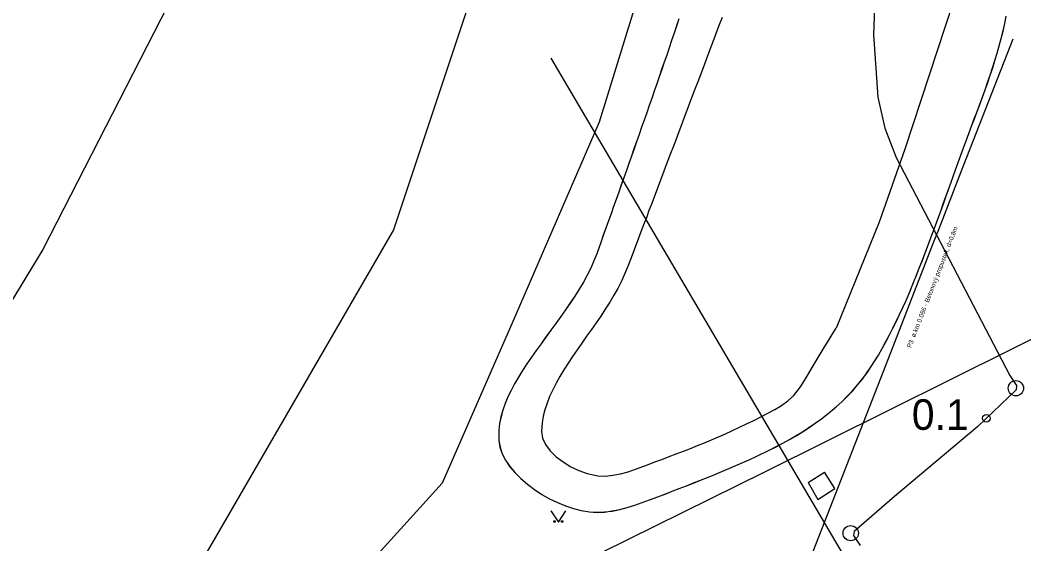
# Model space of a CAD drawing. Extents: x -737422 to -734235, y -1145631 to -1142623.
# Drawn here: x -735091.9 to -735026.3, y -1143091 to -1143056.7 of the extents above; entities that cross this region are included whole.
import ezdxf

# ---------------------------------------------------------------- set-up
doc = ezdxf.new("R2010")
doc.units = 0
for name, color, linetype in [('Vrstva 1', 7, 'Continuous'), ('Vrstva 2', 7, 'Continuous'), ('Vrstva 20', 7, 'Continuous'), ('Vrstva 22', 7, 'Continuous'), ('Vrstva 3', 7, 'Continuous'), ('Vrstva 40', 7, 'Continuous'), ('Vrstva 6', 7, 'Continuous'), ('Vrstva 7', 7, 'Continuous'), ('Vrstva 8', 7, 'Continuous')]:
    doc.layers.add(name, color=color, linetype=linetype)

# ---------------------------------------------------------------- blocks, each defined once
blk = doc.blocks.new('1.050')
at = {"layer": 'Vrstva 1'}
for radius in [0.5, 0.001]:
    blk.add_circle((0, 0), radius, dxfattribs=at)
blk = doc.blocks.new('6.200')
at = {"layer": 'Vrstva 1'}
blk.add_circle((0, 0), 1, dxfattribs=at)
blk = doc.blocks.new('3.140')
at = {"layer": 'Vrstva 1'}
blk.add_lwpolyline([(-1, 1.5), (0, 0), (1, 1.5)], dxfattribs=at)
for centre in [(-0.5, 0.1), (0.5, 0.1)]:
    blk.add_circle(centre, 0.1, dxfattribs=at)

msp = doc.modelspace()

# ---------------------------------------------------------------- linework, layer by layer
at = {"layer": 'Vrstva 2'}
for points in [[(-735047.84, -1142987.81), (-735035.74, -1143023.25), (-735035.52, -1143024.84), (-735035.34, -1143033.99), (-735035.46, -1143039.98), (-735036.11, -1143057.68), (-735035.82, -1143061.77), (-735035.37, -1143063.8), (-735034.62, -1143065.72), (-735027.19, -1143079.99), (-735026.74, -1143080.64), (-735026.77, -1143080.92), (-735029.28, -1143083.32), (-735034.74, -1143087.91), (-735037.38, -1143090.19), (-735037.41, -1143090.46), (-735036.99, -1143091.1)], [(-735062.19, -1143054.47), (-735067.52, -1143070.46), (-735083.15, -1143097.45), (-735109.45, -1143130.12), (-735117, -1143136.7), (-735131.48, -1143149.3), (-735161.32, -1143169.9), (-735197.01, -1143189.05), (-735200.15, -1143191.6), (-735226.32, -1143212.89), (-735242.32, -1143233.92), (-735251.01, -1143259.51), (-735252.721, -1143271.637)]]:
    msp.add_lwpolyline(points, dxfattribs=at)
at = {"layer": 'Vrstva 20'}
for points in [[(-735049.61, -1143048.97), (-735054.06, -1143063.41)], [(-735030.34, -1143053.87), (-735034.05, -1143065.18)], [(-735046.02, -1143056.56), (-735046.2, -1143057.03), (-735046.37, -1143057.5), (-735046.55, -1143057.97), (-735046.73, -1143058.43), (-735046.9, -1143058.9), (-735047.08, -1143059.37), (-735047.26, -1143059.84), (-735047.43, -1143060.3), (-735047.61, -1143060.77), (-735047.79, -1143061.24), (-735047.97, -1143061.71), (-735048.14, -1143062.17), (-735048.32, -1143062.64), (-735048.5, -1143063.11), (-735048.67, -1143063.58), (-735048.85, -1143064.04), (-735049.03, -1143064.51), (-735049.2, -1143064.98), (-735049.38, -1143065.45), (-735049.56, -1143065.92), (-735049.74, -1143066.38), (-735049.91, -1143066.85), (-735050.09, -1143067.32), (-735050.27, -1143067.79), (-735050.44, -1143068.25), (-735050.62, -1143068.72), (-735050.8, -1143069.19), (-735050.97, -1143069.66), (-735051.15, -1143070.12), (-735051.33, -1143070.59), (-735051.51, -1143071.06), (-735051.68, -1143071.53), (-735051.86, -1143071.99), (-735052.2, -1143072.89), (-735052.39, -1143073.36), (-735052.6, -1143073.82), (-735052.84, -1143074.28), (-735053.1, -1143074.73), (-735053.37, -1143075.19), (-735053.66, -1143075.64), (-735053.96, -1143076.09), (-735054.26, -1143076.54), (-735054.57, -1143076.98), (-735054.88, -1143077.42), (-735055.19, -1143077.86), (-735055.5, -1143078.3), (-735055.8, -1143078.74), (-735056.09, -1143079.18), (-735056.37, -1143079.61), (-735056.63, -1143080.05), (-735056.88, -1143080.48), (-735057.1, -1143080.92), (-735057.3, -1143081.35), (-735057.47, -1143081.79), (-735057.61, -1143082.22), (-735057.72, -1143082.65), (-735057.79, -1143083.09), (-735057.83, -1143083.64), (-735057.76, -1143084.08), (-735057.56, -1143084.5), (-735057.26, -1143084.91), (-735056.87, -1143085.3), (-735056.41, -1143085.64), (-735055.91, -1143085.95), (-735055.38, -1143086.2), (-735054.85, -1143086.39), (-735054.14, -1143086.54), (-735053.65, -1143086.56), (-735053.16, -1143086.51), (-735052.67, -1143086.42), (-735052.17, -1143086.28), (-735051.69, -1143086.12), (-735050.89, -1143085.82), (-735050.42, -1143085.64)], [(-735048.84, -1143056.64), (-735049, -1143057.11), (-735049.16, -1143057.59), (-735049.32, -1143058.06), (-735049.48, -1143058.54), (-735049.64, -1143059.01), (-735049.8, -1143059.48), (-735049.97, -1143059.96), (-735050.13, -1143060.43), (-735050.29, -1143060.9), (-735050.46, -1143061.38), (-735050.62, -1143061.85), (-735050.79, -1143062.32), (-735050.95, -1143062.8), (-735051.11, -1143063.27), (-735051.28, -1143063.74), (-735051.45, -1143064.21), (-735051.61, -1143064.69), (-735051.78, -1143065.16), (-735051.94, -1143065.63), (-735052.11, -1143066.1), (-735052.28, -1143066.57), (-735052.45, -1143067.05), (-735052.61, -1143067.52), (-735052.78, -1143067.99), (-735052.95, -1143068.46), (-735053.12, -1143068.93), (-735053.28, -1143069.4), (-735053.45, -1143069.87), (-735053.62, -1143070.34), (-735053.79, -1143070.81), (-735053.96, -1143071.28), (-735054.22, -1143072.02)], [(-735034.4, -1143075.99), (-735034.19, -1143075.53), (-735033.98, -1143075.08), (-735033.78, -1143074.62), (-735033.48, -1143073.89), (-735033.3, -1143073.42), (-735033.11, -1143072.96), (-735032.93, -1143072.49), (-735032.75, -1143072.03), (-735032.58, -1143071.56), (-735032.4, -1143071.09), (-735032.22, -1143070.63), (-735032.05, -1143070.16), (-735031.88, -1143069.69), (-735031.71, -1143069.22), (-735031.54, -1143068.75), (-735031.37, -1143068.28), (-735031.2, -1143067.81), (-735031.03, -1143067.34), (-735030.74, -1143066.52), (-735030.57, -1143066.05), (-735030.4, -1143065.57), (-735030.22, -1143065.09), (-735030.04, -1143064.62), (-735029.86, -1143064.14), (-735029.69, -1143063.67), (-735029.51, -1143063.19), (-735029.33, -1143062.71), (-735029.15, -1143062.24), (-735028.98, -1143061.76), (-735028.8, -1143061.28), (-735028.64, -1143060.8), (-735028.47, -1143060.33), (-735028.31, -1143059.85), (-735028.16, -1143059.37), (-735028.02, -1143058.89), (-735027.88, -1143058.4), (-735027.75, -1143057.92), (-735027.63, -1143057.44), (-735027.52, -1143056.95), (-735027.42, -1143056.47)], [(-735054.06, -1143063.41), (-735059.55, -1143076.11)], [(-735034.05, -1143065.18), (-735035.74, -1143069.94)], [(-735035.74, -1143069.94), (-735038.55, -1143076.88)], [(-735054.22, -1143072.02), (-735054.4, -1143072.49), (-735054.61, -1143072.95), (-735054.84, -1143073.42), (-735055.09, -1143073.87), (-735055.36, -1143074.33), (-735055.65, -1143074.79), (-735055.95, -1143075.24), (-735056.26, -1143075.69), (-735056.57, -1143076.13), (-735056.89, -1143076.58), (-735057.22, -1143077.02), (-735057.54, -1143077.46), (-735057.86, -1143077.9), (-735058.18, -1143078.34), (-735058.49, -1143078.78), (-735058.79, -1143079.22), (-735059.07, -1143079.65), (-735059.34, -1143080.09), (-735059.59, -1143080.52), (-735059.82, -1143080.96), (-735060.03, -1143081.39), (-735060.21, -1143081.82), (-735060.36, -1143082.25), (-735060.48, -1143082.69), (-735060.57, -1143083.12), (-735060.62, -1143083.55), (-735060.62, -1143084.24), (-735060.55, -1143084.67), (-735060.4, -1143085.11), (-735060.18, -1143085.53), (-735059.9, -1143085.95), (-735059.56, -1143086.35), (-735059.18, -1143086.73), (-735058.75, -1143087.1), (-735058.3, -1143087.44), (-735057.81, -1143087.76), (-735057.31, -1143088.05), (-735056.79, -1143088.3), (-735056.27, -1143088.51), (-735055.74, -1143088.69), (-735055.23, -1143088.82), (-735054.68, -1143088.91), (-735054.19, -1143088.94), (-735053.7, -1143088.92), (-735053.21, -1143088.85), (-735052.71, -1143088.75), (-735052.22, -1143088.62), (-735051.73, -1143088.47), (-735051.24, -1143088.3), (-735050.76, -1143088.13), (-735050.22, -1143087.92), (-735049.75, -1143087.74), (-735049.28, -1143087.56), (-735048.82, -1143087.38), (-735048.35, -1143087.2), (-735047.89, -1143087.02), (-735047.42, -1143086.83), (-735046.96, -1143086.65), (-735046.5, -1143086.46), (-735046.04, -1143086.27), (-735045.58, -1143086.08), (-735045.12, -1143085.88), (-735044.66, -1143085.68), (-735044.21, -1143085.47), (-735043.75, -1143085.26), (-735042.93, -1143084.87), (-735042.48, -1143084.64), (-735042.04, -1143084.41), (-735041.6, -1143084.17), (-735041.17, -1143083.92), (-735040.75, -1143083.66), (-735040.33, -1143083.39), (-735039.92, -1143083.11), (-735039.51, -1143082.82), (-735038.94, -1143082.37), (-735038.55, -1143082.04), (-735038.18, -1143081.7), (-735037.82, -1143081.34), (-735037.47, -1143080.98), (-735037.15, -1143080.6), (-735036.83, -1143080.21), (-735036.53, -1143079.81), (-735036.25, -1143079.4), (-735035.79, -1143078.65), (-735035.54, -1143078.21), (-735035.3, -1143077.77), (-735035.07, -1143077.33), (-735034.84, -1143076.88), (-735034.61, -1143076.43), (-735034.4, -1143075.99)], [(-735059.55, -1143076.11), (-735064.33, -1143087.02)], [(-735022.89, -1143076.19), (-735043.24, -1143086.3)], [(-735050.42, -1143085.64), (-735049.95, -1143085.47), (-735049.48, -1143085.29), (-735049.01, -1143085.11), (-735048.55, -1143084.93), (-735048.09, -1143084.75), (-735047.62, -1143084.57), (-735047.16, -1143084.38), (-735046.7, -1143084.19), (-735046.24, -1143083.99), (-735045.79, -1143083.79), (-735045.33, -1143083.58), (-735044.88, -1143083.37), (-735044.42, -1143083.15), (-735043.94, -1143082.92), (-735043.48, -1143082.69), (-735043.02, -1143082.45), (-735042.57, -1143082.21), (-735042.13, -1143081.94), (-735041.72, -1143081.65), (-735041.35, -1143081.32), (-735040.88, -1143080.73), (-735040.62, -1143080.3), (-735040.36, -1143079.88), (-735040.11, -1143079.45), (-735039.85, -1143079.02), (-735039.59, -1143078.59), (-735039.33, -1143078.16), (-735039.07, -1143077.74), (-735038.81, -1143077.31), (-735038.55, -1143076.88)], [(-735043.24, -1143086.3), (-735057.51, -1143093.35)], [(-735040.39, -1143086.99), (-735039.32, -1143086.31)], [(-735038.64, -1143087.38), (-735039.32, -1143086.31)], [(-735040.39, -1143086.99), (-735039.76, -1143088.09)], [(-735039.76, -1143088.09), (-735038.64, -1143087.38)]]:
    msp.add_lwpolyline(points, dxfattribs=at)
at = {"layer": 'Vrstva 3'}
for points in [[(-735034.121, -1142807.443), (-735041.41, -1142833.15), (-735049.67, -1142873.94), (-735063.61, -1142929.72), (-735068.77, -1142951.92), (-735071.87, -1143011.83), (-735079.1, -1143049.53), (-735090.46, -1143071.74), (-735105.06, -1143095.74), (-735128.12, -1143122.71), (-735156.5, -1143145.42), (-735208.29, -1143180.56), (-735229.22, -1143198.3), (-735243.77, -1143211.78), (-735256.18, -1143225.98), (-735267.54, -1143251.18), (-735270.892, -1143271.893)], [(-735049.61, -1143048.97), (-735054.06, -1143063.41)], [(-735048.835, -1143056.64), (-735048.995, -1143057.114), (-735049.156, -1143057.588), (-735049.317, -1143058.062), (-735049.478, -1143058.536), (-735049.64, -1143059.01), (-735049.803, -1143059.483), (-735049.965, -1143059.957), (-735050.129, -1143060.43), (-735050.292, -1143060.904), (-735050.456, -1143061.377), (-735050.62, -1143061.85), (-735050.785, -1143062.323), (-735050.949, -1143062.796), (-735051.114, -1143063.268), (-735051.28, -1143063.741), (-735051.446, -1143064.213), (-735051.611, -1143064.685), (-735051.778, -1143065.158), (-735051.944, -1143065.63), (-735052.111, -1143066.101), (-735052.278, -1143066.573), (-735052.445, -1143067.045), (-735052.612, -1143067.516), (-735052.779, -1143067.987), (-735052.947, -1143068.458), (-735053.115, -1143068.929), (-735053.282, -1143069.4), (-735053.45, -1143069.87), (-735053.619, -1143070.341), (-735053.787, -1143070.811), (-735053.955, -1143071.281), (-735054.22, -1143072.02)], [(-735034.396, -1143075.985), (-735034.185, -1143075.534), (-735033.98, -1143075.079), (-735033.782, -1143074.622), (-735033.48, -1143073.89), (-735033.295, -1143073.424), (-735033.112, -1143072.959), (-735032.932, -1143072.493), (-735032.752, -1143072.027), (-735032.575, -1143071.561), (-735032.399, -1143071.094), (-735032.224, -1143070.627), (-735032.051, -1143070.16), (-735031.878, -1143069.692), (-735031.707, -1143069.223), (-735031.537, -1143068.753), (-735031.367, -1143068.283), (-735031.198, -1143067.811), (-735031.03, -1143067.339), (-735030.74, -1143066.52), (-735030.57, -1143066.045), (-735030.397, -1143065.569), (-735030.221, -1143065.094), (-735030.043, -1143064.618), (-735029.864, -1143064.142), (-735029.685, -1143063.666), (-735029.505, -1143063.19), (-735029.326, -1143062.714), (-735029.149, -1143062.237), (-735028.975, -1143061.76), (-735028.803, -1143061.282), (-735028.635, -1143060.804), (-735028.472, -1143060.325), (-735028.314, -1143059.846), (-735028.162, -1143059.366), (-735028.017, -1143058.885), (-735027.879, -1143058.404), (-735027.75, -1143057.921), (-735027.629, -1143057.438), (-735027.518, -1143056.954), (-735027.418, -1143056.469)], [(-735054.06, -1143063.41), (-735059.55, -1143076.11)], [(-735054.22, -1143072.02), (-735054.402, -1143072.488), (-735054.61, -1143072.953), (-735054.842, -1143073.415), (-735055.094, -1143073.874), (-735055.364, -1143074.331), (-735055.649, -1143074.785), (-735055.948, -1143075.236), (-735056.256, -1143075.686), (-735056.573, -1143076.133), (-735056.894, -1143076.579), (-735057.218, -1143077.022), (-735057.542, -1143077.464), (-735057.863, -1143077.904), (-735058.179, -1143078.343), (-735058.488, -1143078.781), (-735058.785, -1143079.217), (-735059.07, -1143079.653), (-735059.339, -1143080.088), (-735059.59, -1143080.521), (-735059.821, -1143080.955), (-735060.027, -1143081.388), (-735060.208, -1143081.821), (-735060.36, -1143082.253), (-735060.482, -1143082.686), (-735060.569, -1143083.118), (-735060.62, -1143083.551), (-735060.62, -1143084.24), (-735060.546, -1143084.674), (-735060.397, -1143085.105), (-735060.178, -1143085.53), (-735059.897, -1143085.945), (-735059.561, -1143086.348), (-735059.178, -1143086.734), (-735058.753, -1143087.1), (-735058.295, -1143087.443), (-735057.81, -1143087.76), (-735057.305, -1143088.046), (-735056.788, -1143088.298), (-735056.265, -1143088.514), (-735055.744, -1143088.689), (-735055.231, -1143088.82), (-735054.68, -1143088.91), (-735054.193, -1143088.937), (-735053.702, -1143088.915), (-735053.208, -1143088.851), (-735052.714, -1143088.752), (-735052.22, -1143088.623), (-735051.728, -1143088.472), (-735051.241, -1143088.304), (-735050.759, -1143088.126), (-735050.22, -1143087.92), (-735049.752, -1143087.74), (-735049.284, -1143087.56), (-735048.818, -1143087.38), (-735048.352, -1143087.199), (-735047.887, -1143087.017), (-735047.424, -1143086.834), (-735046.961, -1143086.649), (-735046.499, -1143086.462), (-735046.039, -1143086.272), (-735045.579, -1143086.078), (-735045.12, -1143085.881), (-735044.662, -1143085.68), (-735044.206, -1143085.474), (-735043.75, -1143085.264), (-735042.93, -1143084.87), (-735042.48, -1143084.644), (-735042.037, -1143084.411), (-735041.6, -1143084.171), (-735041.17, -1143083.922), (-735040.746, -1143083.663), (-735040.328, -1143083.393), (-735039.915, -1143083.111), (-735039.508, -1143082.815), (-735038.94, -1143082.37), (-735038.551, -1143082.039), (-735038.176, -1143081.697), (-735037.818, -1143081.344), (-735037.474, -1143080.979), (-735037.146, -1143080.602), (-735036.832, -1143080.214), (-735036.534, -1143079.814), (-735036.25, -1143079.401), (-735035.79, -1143078.65), (-735035.543, -1143078.209), (-735035.301, -1143077.768), (-735035.066, -1143077.325), (-735034.837, -1143076.88), (-735034.614, -1143076.434), (-735034.396, -1143075.985)], [(-735059.55, -1143076.11), (-735064.33, -1143087.02)], [(-735069.15, -1143092.35), (-735064.33, -1143087.02)]]:
    msp.add_lwpolyline(points, dxfattribs=at)
at = {"layer": 'Vrstva 40'}
msp.add_lwpolyline([(-735036.97, -1143093.57), (-735057.19, -1143059.22)], dxfattribs=at)
at = {"layer": 'Vrstva 8'}
msp.add_lwpolyline([(-735040.22, -1143091.94), (-735035.28, -1143079.26), (-735032.13, -1143071.18), (-735031.98, -1143070.81), (-735031.98, -1143070.8), (-735031.84, -1143070.43), (-735030.4, -1143066.69), (-735026.97, -1143057.95)], dxfattribs=at)

# ---------------------------------------------------------------- block references
at = {"layer": 'Vrstva 20', "xscale": 0.5, "yscale": 0.5}
for name, p in [('6.200', (-735026.79, -1143080.82)), ('3.140', (-735056.73, -1143089.59)), ('6.200', (-735037.6, -1143090.3))]:
    msp.add_blockref(name, p, dxfattribs=at)
at = {"layer": 'Vrstva 6', "xscale": 0.5, "yscale": 0.5}
msp.add_blockref('1.050', (-735028.72, -1143082.78), dxfattribs=at)

# ---------------------------------------------------------------- texts
at = {"layer": 'Vrstva 22'}
msp.add_text('P3  ø.km 0.086 - Betonový propustek, d=0,8m', height=0.3, rotation=68.776, dxfattribs=at).set_placement((-735033.65, -1143078.2))
at = {"layer": 'Vrstva 7'}
msp.add_text('0.1', height=2, dxfattribs=at).set_placement((-735033.6, -1143083.54))

doc.saveas('drawing.dxf')
